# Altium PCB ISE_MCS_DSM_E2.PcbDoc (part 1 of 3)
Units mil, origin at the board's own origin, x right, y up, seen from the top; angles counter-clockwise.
Board outline 7874.02 x 2559.06 mil, 4 copper layers (Top Layer, MidLayer1, MidLayer2, Bottom Layer), stack 61.2 mil thick; 400 components, 190 nets, 1028 pads, 191 vias.
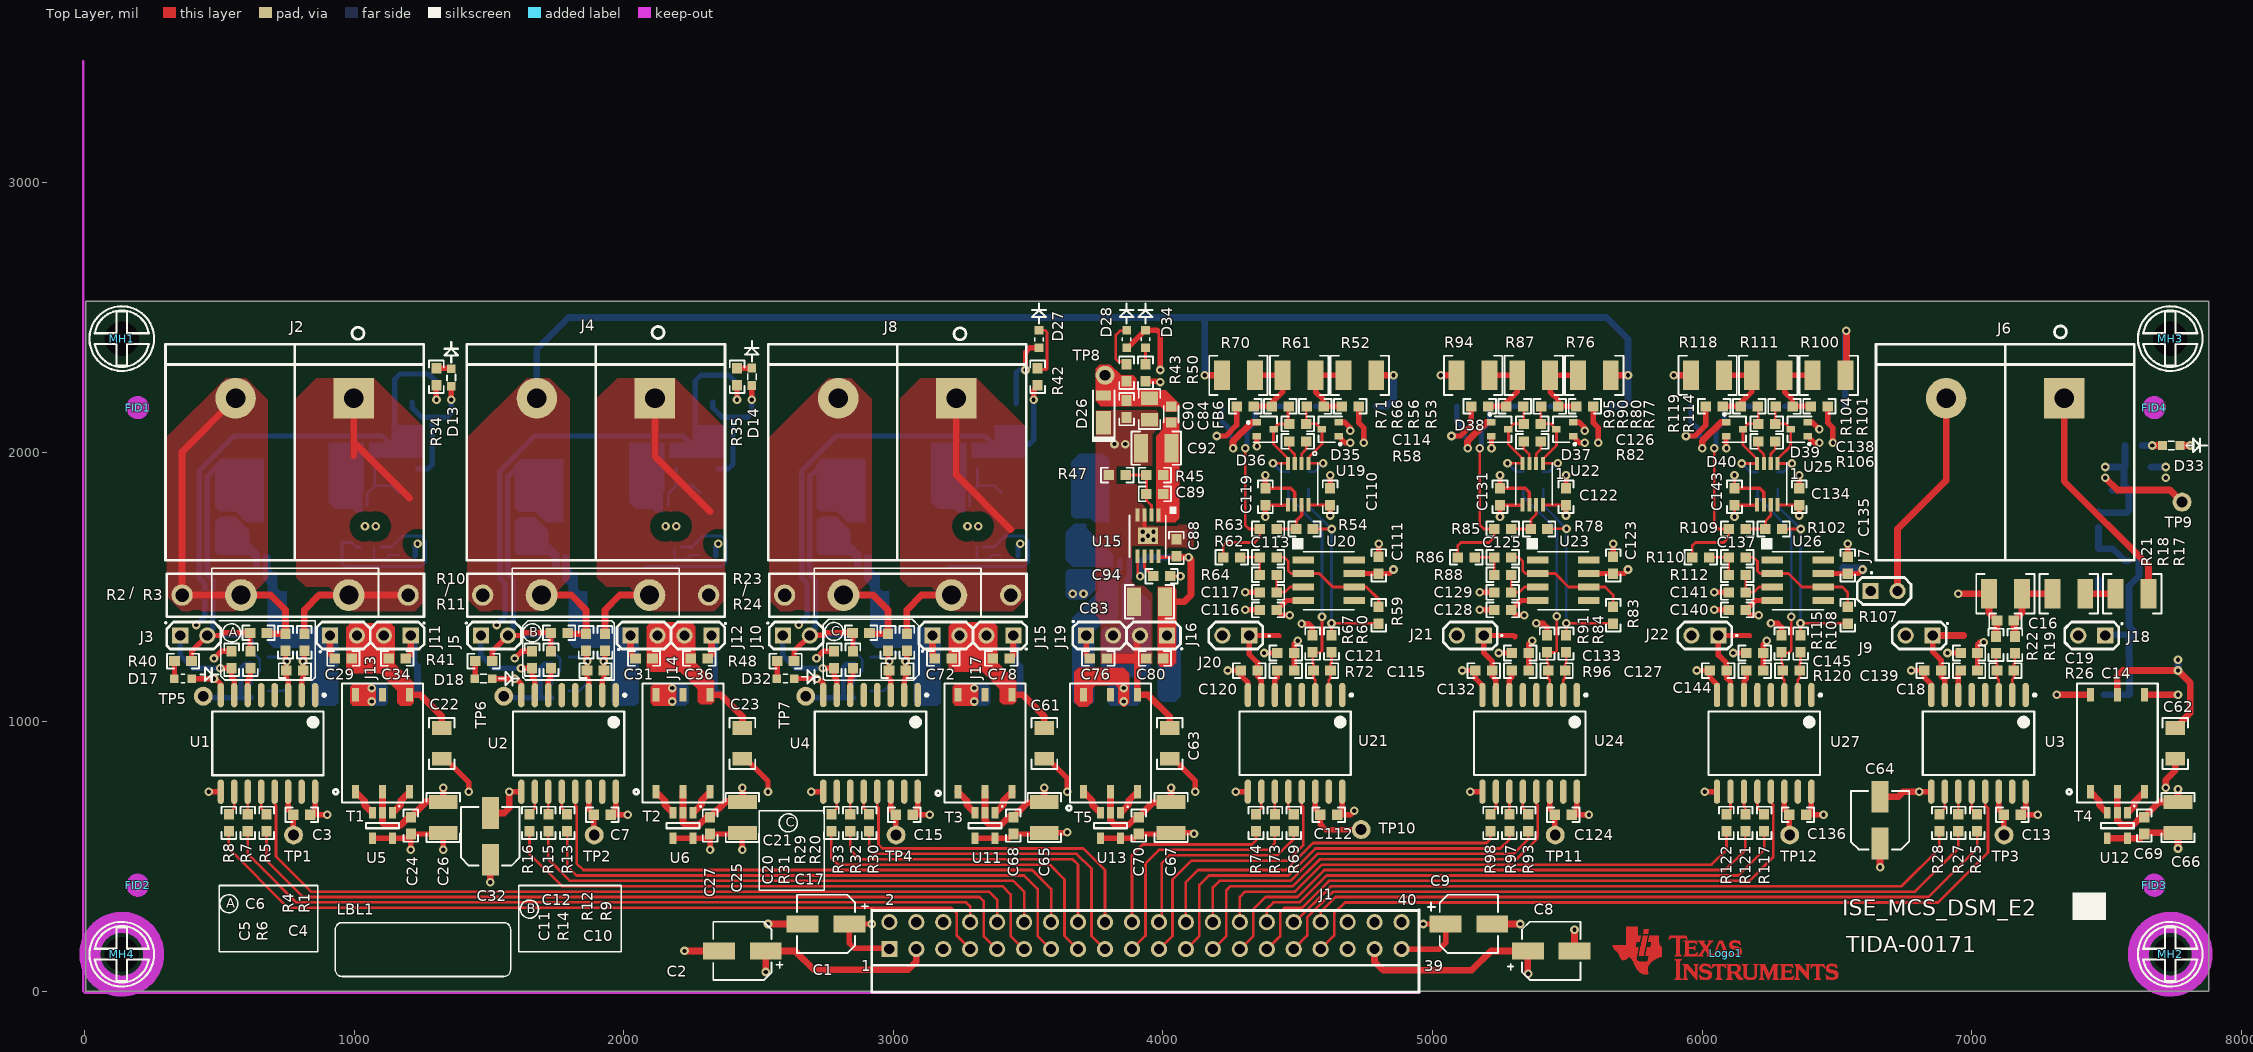
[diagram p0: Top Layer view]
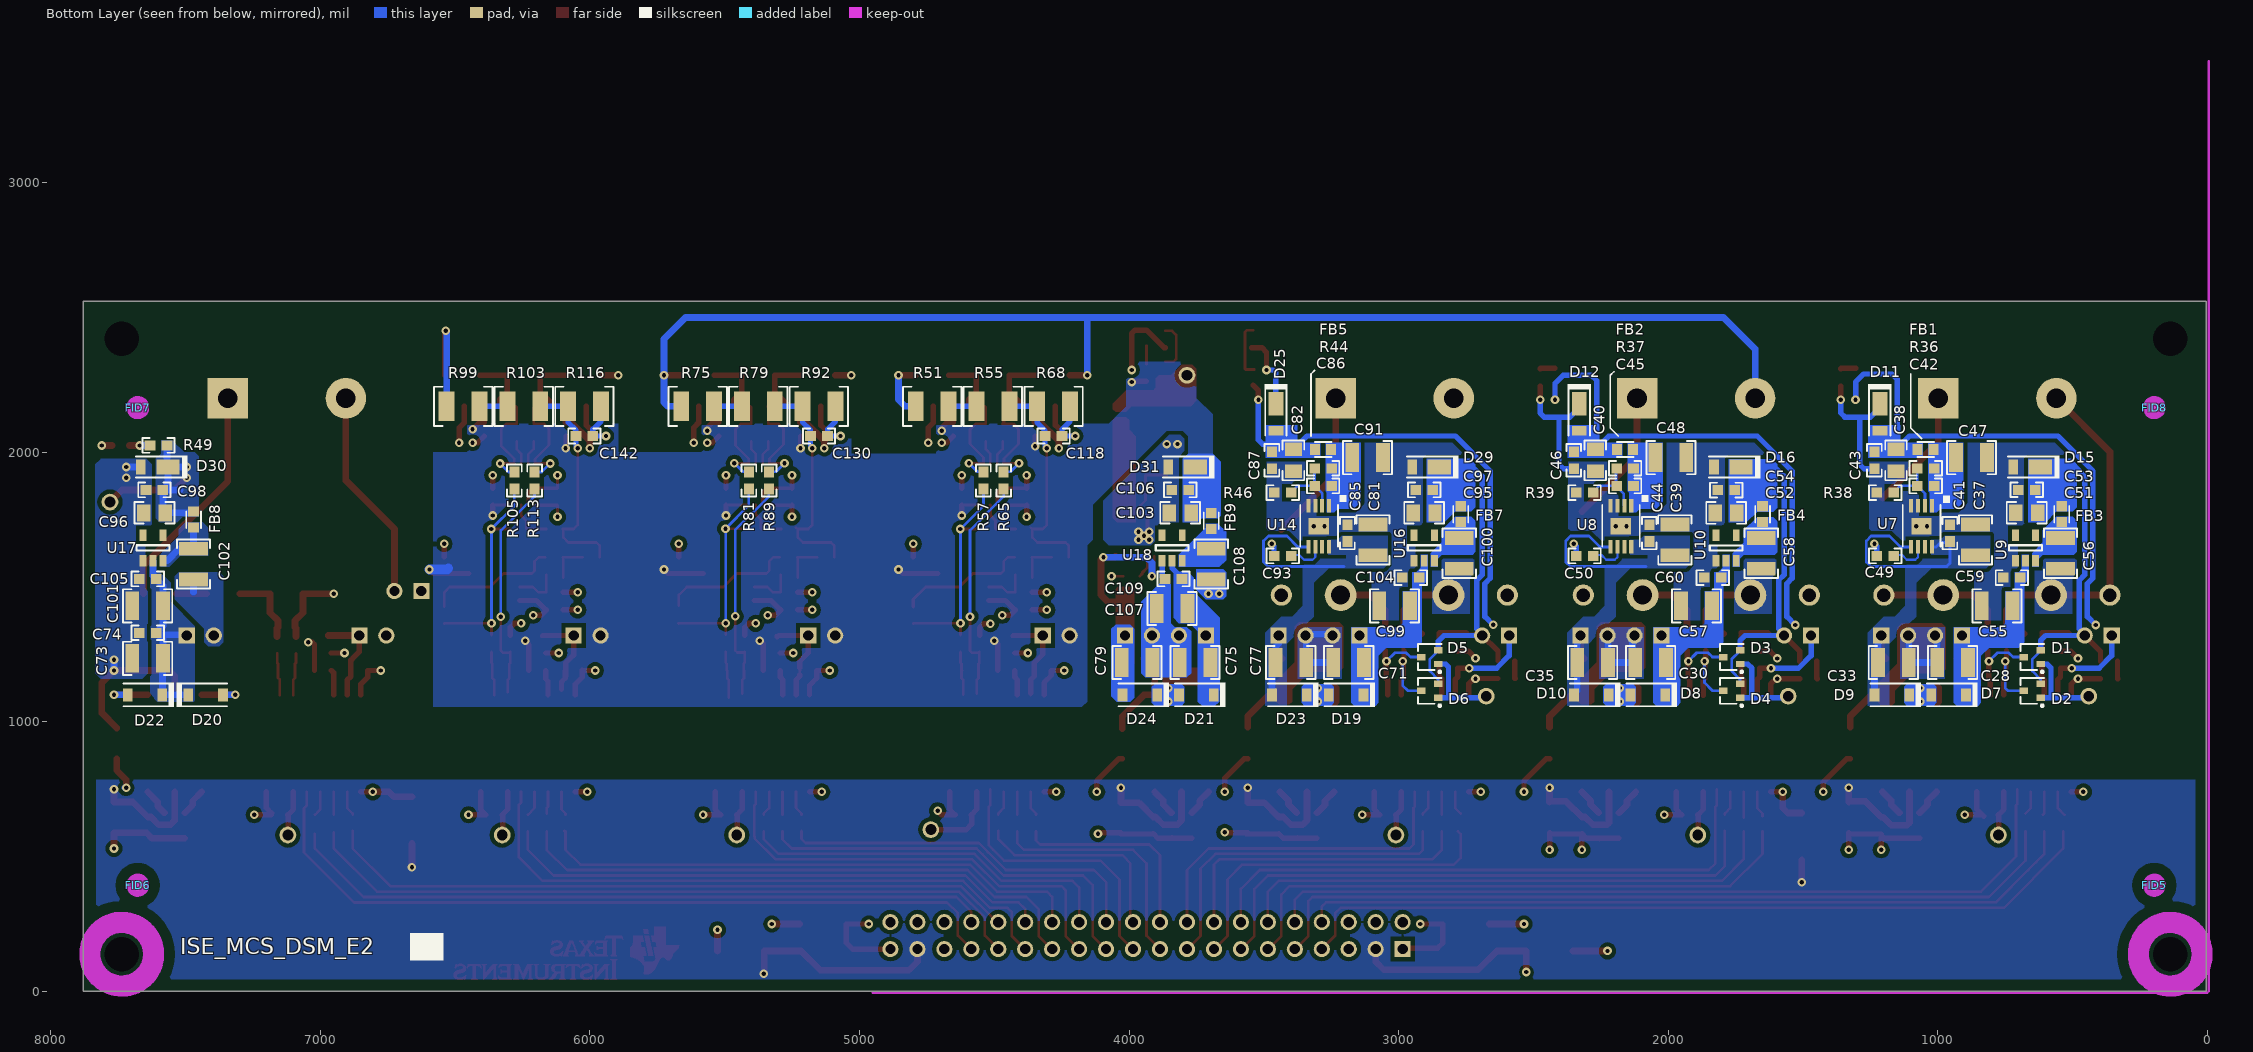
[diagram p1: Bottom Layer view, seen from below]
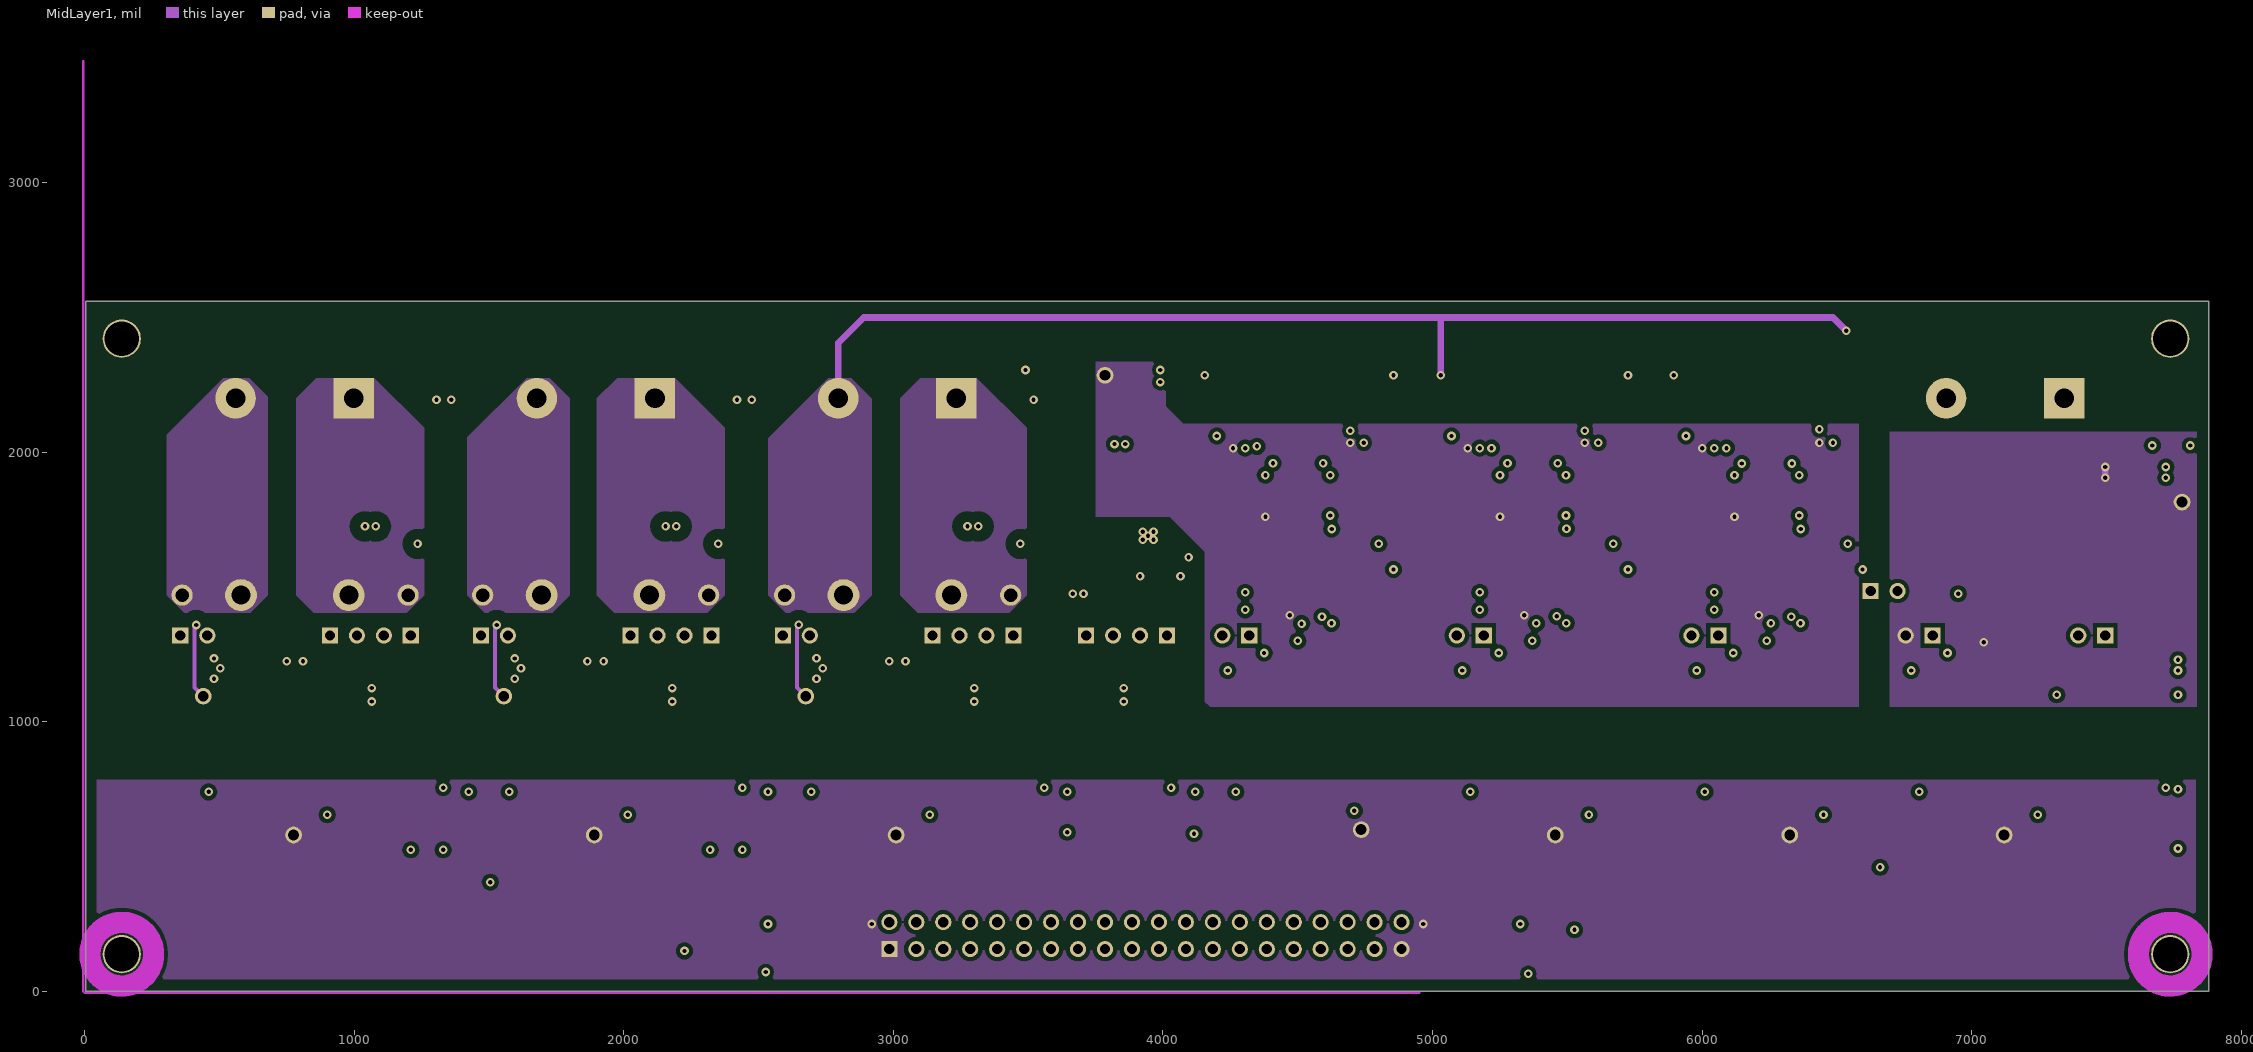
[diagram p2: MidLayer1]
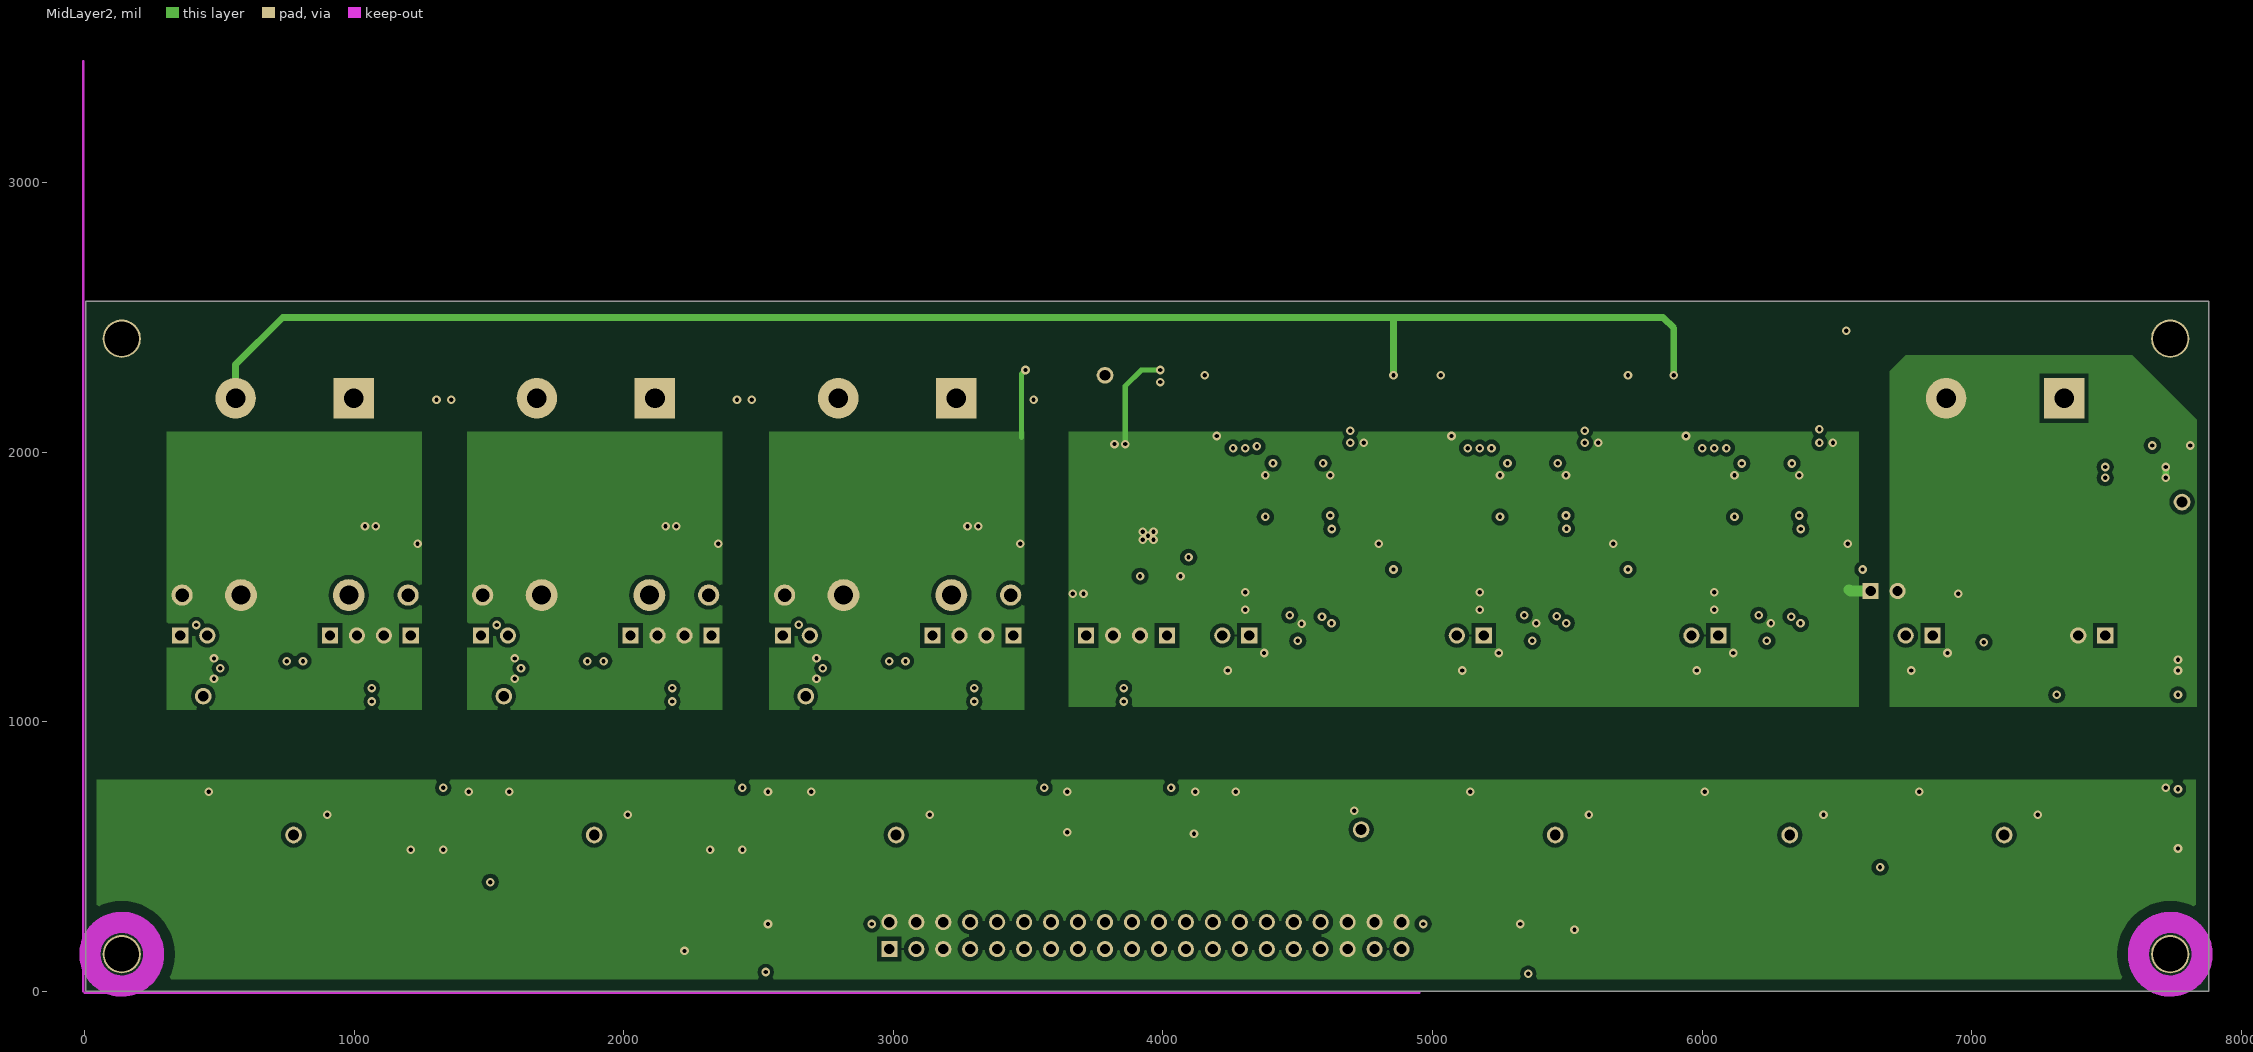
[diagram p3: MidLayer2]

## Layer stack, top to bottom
Top Layer: signal copper 2.8
Dielectric: core 16.6, FR-4, Dk 4.8
MidLayer1: signal copper 2.8
Dielectric: prepreg 16.8, FR-4, Dk 4.8
MidLayer2: signal copper 2.8
Dielectric: core 16.6, FR-4, Dk 4.8
Bottom Layer: signal copper 2.8

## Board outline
5,0 5,2559.06 7879.02,2559.06 7879.02,0

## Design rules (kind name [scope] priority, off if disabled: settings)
AcuteAngle [All] p1 off: minimum=4.50000000000000E+0001 checktracksonly=FALSE
AssemblyTestPointUsage [All] p1 off: valid=2
AssemblyTestpoint [All] p1 off: testpointundercomponent=TRUE minsize=40 maxsize=100 preferedsize=60 minholesize=0 maxholesize=40 preferedholesize=32 testpointgrid=1 usegrid=TRUE gridtolerance=0.01 allowsidetop=TRUE allowsidebottom=TRUE
Clearance Clearance_35 [IsVia vs IsVia] p1: gap=3
Clearance Clearance_34 [InNamedPolygon('MidLayer1-No Net 7')] p2: gap=40
Clearance Clearance_33 [InNamedPolygon('MidLayer1-No Net 6')] p3: gap=40
Clearance Clearance_32 [InNamedPolygon('MidLayer1-No Net 5')] p4: gap=40
Clearance Clearance_31 [InNamedPolygon('Top Layer-No Net 6')] p5: gap=40
Clearance Clearance_30 [InNamedPolygon('Top Layer-No Net 5')] p6: gap=40
Clearance Clearance_29 [InNamedPolygon('Top Layer-No Net 4')] p7: gap=40
Clearance Clearance_28 [InNamedPolygon('MidLayer1-No Net 4')] p8: gap=40
Clearance Clearance_27 [InNamedPolygon('MidLayer1-No Net 3')] p9: gap=40
Clearance Clearance_26 [InNamedPolygon('Top Layer-No Net 3')] p10: gap=40
Clearance Clearance_25 [InNamedPolygon('Top Layer-No Net 2')] p11: gap=40
Clearance Clearance_24 [InNamedPolygon('Top Layer-No Net 1')] p12: gap=40
Clearance Clearance_23 [InNamedPolygon('MidLayer1-No Net 2')] p13: gap=40
Clearance Clearance_22 [InNamedPolygon('MidLayer1-No Net 2')] p14: gap=40
Clearance Clearance_21 [InNamedPolygon('MidLayer1-No Net 2')] p15: gap=15
Clearance Clearance_20 [InNamedPolygon('MidLayer1-No Net 2')] p16: gap=40
Clearance Clearance_19 [InNamedPolygon('MidLayer1-No Net 2')] p17: gap=40
Clearance Clearance_18 [InNamedPolygon('MidLayer1-No Net 2')] p18: gap=15
Clearance Clearance_17 [InNamedPolygon('MidLayer1-No Net 2')] p19: gap=40
Clearance Clearance_16 [InNamedPolygon('MidLayer1-No Net 2')] p20: gap=40
Clearance Clearance_15 [InNamedPolygon('MidLayer1-No Net 2')] p21: gap=40
Clearance Clearance_14 [InNamedPolygon('MidLayer1-No Net 2')] p22: gap=40
Clearance Clearance_13 [InNamedPolygon('MidLayer1-No Net 2')] p23: gap=40
Clearance Clearance_12 [InNamedPolygon('MidLayer1-No Net 2')] p24: gap=40
Clearance Clearance_11 [InNamedPolygon('MidLayer1-No Net 2')] p25: gap=40
Clearance Clearance_10 [InNamedPolygon('MidLayer1-No Net 2')] p26: gap=40
Clearance Clearance_9 [InNamedPolygon('MidLayer1-No Net 2')] p27: gap=15
Clearance Clearance_8 [InNamedPolygon('MidLayer1-No Net 2')] p28: gap=40
Clearance Clearance_7 [InNamedPolygon('MidLayer1-No Net 2')] p29: gap=40
Clearance Clearance_6 [InNamedPolygon('MidLayer1-No Net 2')] p30: gap=40
Clearance Clearance_5 [InNamedPolygon('MidLayer1-No Net 2')] p31: gap=40
Clearance Clearance_4 [InNamedPolygon('MidLayer1-No Net')] p32: gap=15
Clearance Clearance_3 [InNamedPolygon('MidLayer1-No Net')] p33: gap=10
Clearance Clearance_2 [InNamedPolygon('MidLayer1-No Net')] p34: gap=10
Clearance Clearance_1 [InNamedPolygon('MidLayer1-No Net')] p35: gap=40
Clearance Clearance_BoardEdge_MountingHoles [OnCopper and InComponentClass('Mounting Holes') vs IsKeepOut] p36: gap=40
Clearance Clearance_BoardEdge_Poly [OnCopper and InPoly vs IsKeepOut] p37: gap=40
Clearance Clearance_BoardEdge [OnCopper and Not InComponentClass('Logo') and not InComponentClass('FiducialMark') and not InRegion(1000,500,4000,800) and Not IsKeepout vs IsKeepOut] p38: gap=40
Clearance Clearance_Poly [InPolygon] p39: gap=15
Clearance [All] p40: gap=8
ComponentClearance ComponentClearance_Logo [InComponentClass('Logo')] p1 off: gap=50 collisioncheckmode=3 verticalgap=10 showdistances=FALSE
ComponentClearance ComponentClearance_ScrewToNut [(HasFootprint('NY PMS 440 0025 PH')) vs (HasFootprint('Keystone_1902C'))] p2 off: gap=5 collisioncheckmode=3 verticalgap=10 showdistances=FALSE
ComponentClearance ComponentClearance_MountingHoles [InComponentClass('Mounting Holes')] p3 off: gap=250 collisioncheckmode=3 verticalgap=100000 showdistances=FALSE
ComponentClearance ComponentClearance_SmallPassives [HasFootprint('0201*') or HasFootprint('0402*') or HasFootprint('0508') or HasFootprint('0603*') or HasFootprint('0612') or HasFootprint('0805*') or HasFootprint('0815*') or HasFootprint('0830*') or HasFootprint('1206*') or HasFootprint('1210*') or HasFootprint('1808*') or HasFootprint('1812*') or HasFootprint('1825*') or HasFootprint('2010*') or HasFootprint('2220*') or HasFootprint('2225*') or HasFootprint('2512*') or HasFootprint('2728*') or HasFootprint('3518*') vs HasFootprint('0201*') or HasFootprint('0402*') or HasFootprint('0508') or HasFootprint('0603*') or HasFootprint('0612') or HasFootprint('0805*') or HasFootprint('0815*') or HasFootprint('0830*') or HasFootprint('1206*') or HasFootprint('1210*') or HasFootprint('1808*') or HasFootprint('1812*') or HasFootprint('1825*') or HasFootprint('2010*') or HasFootprint('2220*') or HasFootprint('2225*') or HasFootprint('2512*') or HasFootprint('2728*') or HasFootprint('3518*')] p4 off: gap=20 collisioncheckmode=3 verticalgap=10 showdistances=FALSE
ComponentClearance ComponentClearance_THtoSMT [IsThruComponent vs IsSMTComponent] p5 off: gap=100 collisioncheckmode=3 verticalgap=30 showdistances=FALSE
ComponentClearance ComponentClearance_THtoTH [IsThruComponent vs IsThruComponent] p6 off: gap=118.11 collisioncheckmode=3 verticalgap=30 showdistances=FALSE
ComponentClearance [All] p7 off: gap=40 collisioncheckmode=3 verticalgap=10 showdistances=FALSE
DiffPairsRouting DiffPair_RS232DiffPairsRouting [InDifferentialPair ('RS232')] p1: maxlimit=8 minlimit=8 mostfreqgap=8 maxuncoupledlength=500
DiffPairsRouting [All] p2: maxlimit=100 minlimit=10 mostfreqgap=10 maxuncoupledlength=1000
FabricationTestPointUsage TestPointUsage [All] p1 off: valid=2 allowmultiple=FALSE
FabricationTestpoint Testpoint [All] p1 off: side=3 testpointundercomponent=TRUE minsize=40 maxsize=100 preferedsize=60 minholesize=0 maxholesize=40 preferedholesize=32 testpointgrid=1 allowsidetop=TRUE allowsidebottom=TRUE usegrid=TRUE gridtolerance=0.01
FanoutControl Fanout_LCC [IsLCC] p1 off: bgadir=Out bgaviamode=Centered fanoutstyle=Auto fanoutdirection=Alternating viagrid=1 // Fanout_LCC (Default Rule)
FanoutControl Fanout_BGA [IsBGA] p2 off: bgadir=Out bgaviamode=Centered fanoutstyle=Auto fanoutdirection=Alternating viagrid=1 // Fanout_BGA (Default Rule)
FanoutControl Fanout_SOIC [IsSOIC] p3 off: bgadir=Out bgaviamode=Centered fanoutstyle=Auto fanoutdirection=Alternating viagrid=1 // Fanout_SOIC (Default Rule)
FanoutControl Fanout_Default [All] p4 off: bgadir=Out bgaviamode=Centered fanoutstyle=Auto fanoutdirection=Alternating viagrid=1 // Fanout_Default (Default Rule)
FanoutControl Fanout_Small [(CompPinCount < 5)] p5 off: bgadir=Out bgaviamode=Centered fanoutstyle=Auto fanoutdirection=OutThenIn viagrid=1 // Fanout_Small (Default Rule)
Height [All] p1 off: minheight=0 maxheight=1000 prefheight=500
HoleSize [All] p1 off: absolutevalues=TRUE maxlimit=251 minlimit=8 maxpercent=80.000 minpercent=20.000
HoleToHoleClearance [All] p1 off: gap=10 allowstackedmicrovias=TRUE
LayerPairs [All] p1 off: enforce=TRUE
MatchedLengths DiffPair_RS232MatchedLengths [InDifferentialPair ('RS232')] p1: tolerance=1000 checknetsindiffpair=TRUE checkdiffpairvsdiffpair=TRUE checkothers=TRUE
MinimumAnnularRing MinimumAnnularRing_ThermalPadVias [IsVia and InAnyComponent] p1 off: minimumring=5.91
MinimumAnnularRing [All] p2 off: minimumring=8
MinimumSolderMaskSliver MinimumSolderMaskSliver_Logo [InComponentClass('Logo') vs InComponentClass('Logo')] p1 off: minsoldermaskwidth=0.7
MinimumSolderMaskSliver [All] p2 off: minsoldermaskwidth=3.94
NetAntennae [All] p1 off: netantennaetolerance=0
PasteMaskExpansion [All] p1 off: expansion=0
PlaneClearance [All] p1: clearance=15
PlaneConnect [All] p1: planeconnectstyle=Direct reliefexpansion=10 reliefentries=4 reliefconductorwidth=10 reliefairgap=10
PolygonConnect [All] p1: connectstyle=Direct reliefconductorwidth=10 reliefentries=4 polygonreliefangle="90 Angle" airgapwidth=10
RoutingCorners [All] p1 off: cornerstyle=45-Degree minsetback=100 maxsetback=100
RoutingLayers [All] p1 off: top layer_v5=TRUE mid layer 1_v5=TRUE mid layer 2_v5=TRUE bottom layer_v5=TRUE
RoutingPriority [All] p1 off: routingpriority=0
RoutingTopology [All] p1 off: topology=Shortest
RoutingVias ThermalPadVias [IsVia and InAnyComponent] p1: holewidth=16 width=32 viastyle="Through Hole" minholewidth=16 minwidth=32 maxholewidth=16 maxwidth=32
RoutingVias [All] p2: holewidth=16 width=32 viastyle="Through Hole" minholewidth=16 minwidth=32 maxholewidth=16 maxwidth=32
SMDToCorner [All] p1 off: distance=30000
SilkToSilkClearance [All] p1 off: silktosilkclearance=5
SilkscreenOverComponentPads [All] p1 off: minsilkscreentomaskgap=5
SolderMaskExpansion [All] p1 off: expansion=1.97
Width DiffPair_RS232Width [InDifferentialPair('RS232')] p1: maxlimit=10 minlimit=10 preferedwidth=10
Width [All] p2: maxlimit=100 minlimit=8 preferedwidth=25 checkconnectedcopper=TRUE
2 further rules are at their usual default settings.

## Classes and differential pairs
component class "Current Sense": C1 C2 C3 C4 C5 C6 C7 C8 C9 C10 C11 C12 C13 C14 C15 C16 C17 C18 C19 C20 C21 D1 D2 D3 D4 D5 D6 J1 J2 J3 J4 J5 J6 J7 J8 J9 J10 R1 R2 R3 R4 R5 R6 R7 R8 R9 R10 R11 R12 R13 R14 R15 R16 R17 R18 R19 R20 R21 R22 R23 R24 R25 R26 R27 R28 R29 R30 R31 R32 R33 TP1 TP2 TP3 TP4 U1 U2 U3 U4
component class "Mounting Holes": MH1 MH2 MH3 MH4
component class Logo: Logo1
component class Hardware: FID1 FID2 FID3 FID4 FID5 FID6 FID7 FID8 LBL1 Logo1 MH1 MH2 MH3 MH4 ZZ1 ZZ2 ZZ3 ZZ4
component class FiducialMark: FID1 FID2 FID3 FID4 FID5 FID6 FID7 FID8
component class AssemblyNote: ZZ1 ZZ2 ZZ3 ZZ4
component class Label: LBL1
component class "Voltage signal conditioning": C110 C111 C112 C113 C114 C115 C116 C117 C118 C119 C120 C121 C122 C123 C124 C125 C126 C127 C128 C129 C130 C131 C132 C133 C134 C135 C136 C137 C138 C139 C140 C141 C142 C143 C144 C145 D35 D36 D37 D38 D39 D40 J20 J21 J22 R51 R52 R53 R54 R55 R56 R57 R58 R59 R60 R61 R62 R63 R64 R65 R66 R67 R68 R69 R70 R71 R72 R73 R74 R75 R76 R77 R78 R79 R80 R81 R82 R83 R84 R85 R86 R87 R88 R89 R90 R91 R92 R93 R94 R95 R96 R97 R98 R99 R100 R101 R102 R103 R104 R105 R106 R107 R108 R109 R110 R111 R112 R113 R114 R115 R116 R117 R118 R119 R120 R121 R122 TP10 TP11 TP12 U19 U20 U21 U22 U23 U24 U25 U26 U27
component class "Power supply 1": C22 C23 C24 C25 C26 C27 C28 C29 C30 C31 C32 C33 C34 C35 C36 C37 C38 C39 C40 C41 C42 C43 C44 C45 C46 C47 C48 C49 C50 C51 C52 C53 C54 C55 C56 C57 C58 C59 C60 D7 D8 D9 D10 D11 D12 D13 D14 D15 D16 D17 D18 FB1 FB2 FB3 FB4 J11 J12 J13 J14 R34 R35 R36 R37 R38 R39 R40 R41 T1 T2 TP5 TP6 U5 U6 U7 U8 U9 U10
component class "Power supply 2": C61 C62 C63 C64 C65 C66 C67 C68 C69 C70 C71 C72 C73 C74 C75 C76 C77 C78 C79 C80 C81 C82 C83 C84 C85 C86 C87 C88 C89 C90 C91 C92 C93 C94 C95 C96 C97 C98 C99 C100 C101 C102 C103 C104 C105 C106 C107 C108 C109 D19 D20 D21 D22 D23 D24 D25 D26 D27 D28 D29 D30 D31 D32 D33 D34 FB5 FB6 FB7 FB8 FB9 J15 J16 J17 J18 J19 R42 R43 R44 R45 R46 R47 R48 R49 R50 T3 T4 T5 TP7 TP8 TP9 U11 U12 U13 U14 U15 U16 U17 U18

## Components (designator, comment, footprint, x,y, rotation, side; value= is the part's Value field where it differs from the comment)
C1 "UUD1E220MCL1GS" SM_RADIAL_5MM 2750,250 r180 top
C2 "UUD1E220MCL1GS" SM_RADIAL_5MM 2440,150 r180 top
C3 "" 0603 805,655 r180 top
C4 "C1608C0G1E392J" 0603 780,1190 r180 top
C5 "" 0603 545,1230 r90 top
C6 "" 0603 645,1330 r0 top
C7 "" 0603 1920,655 r180 top
C8 "UUD1E220MCL1GS" SM_RADIAL_5MM 5440,150 r0 top
C9 "UUD1E220MCL1GS" SM_RADIAL_5MM 5135,250 r0 top
C10 "C1608C0G1E392J" 0603 1895,1190 r180 top
C11 "" 0603 1660,1230 r90 top
C12 "" 0603 1760,1330 r0 top
C13 "" 0603 7150,655 r180 top
C14 "" 0603 7125,1190 r180 top
C15 "" 0603 3040,655 r180 top
C16 "" 0603 7125,1375 r0 top
C17 "C1608C0G1E392J" 0603 3015,1190 r180 top
C18 "" 0603 6855,1190 r180 top
C19 "" 0603 6990,1255 r180 top
C20 "" 0603 2780,1230 r90 top
C21 "" 0603 2880,1330 r0 top
C22 "" 1206 1325,920 r90 top
C23 "" 1206 2440,920 r90 top
C24 "" 1210 1330,645 r90 top
C25 "" 1210 2440,645 r90 top
C26 "" 0603 1210,615 r90 top
C27 "" 0603 2320,615 r90 top
C28 "" 1210 945,1220 r0 bottom
C29 "" 0603 960,1235 r0 top
C30 "" 1210 2065,1220 r0 bottom
C31 "" 0603 2075,1235 r0 top
C32 "UUD1E220MCL1GS" SM_RADIAL_5MM 1505,575 r90 top
C33 "" 1210 1165,1220 r0 bottom
C34 "" 0603 1160,1235 r0 top
C35 "" 1210 2280,1220 r0 bottom
C36 "" 0603 2280,1235 r0 top
C37 "" 1210 860,1675 r270 bottom
C38 "" 0805_HV 1155,1970 r90 bottom
C39 "" 1210 1975,1675 r270 bottom
C40 "" 0805_HV 2270,1970 r90 bottom
C41 "" 0603 955,1700 r90 bottom
C42 "" 0603 1045,1875 r180 bottom
C43 "" 0603 1235,1970 r270 bottom
C44 "" 0603 2070,1700 r90 bottom
C45 "" 0603 2160,1875 r180 bottom
C46 "" 0603 2350,1970 r270 bottom
C47 "" 1210 875,1980 r0 bottom
C48 "" 1210 1990,1980 r0 bottom
C49 "" 0603 1195,1615 r180 bottom
C50 "" 0603 2310,1615 r180 bottom
C51 "" 0805_HV 670,1775.32 r180 bottom
C52 "" 0805_HV 1785,1774.5 r180 bottom
C53 "" 0603 670,1860.32 r0 bottom
C54 "" 0603 1785,1859.5 r0 bottom
C55 "" 1210 780,1430 r180 bottom
C56 "" 1210 545,1625 r90 bottom
C57 "" 1210 1895,1430 r180 bottom
C58 "" 1210 1655,1625 r90 bottom
C59 "" 0603 725,1535 r0 bottom
C60 "" 0603 1835,1535 r0 bottom
C61 "" 1206 3560,920 r90 top
C62 "" 1206 7755,920 r90 top
C63 "" 1206 4025,920 r90 top
C64 "UUD1E220MCL1GS" SM_RADIAL_5MM 6660,635 r90 top
C65 "" 1210 3560,645 r90 top
C66 "" 1210 7765,645 r90 top
C67 "" 1210 4030,645 r90 top
C68 "" 0603 3445,615 r90 top
C69 "" 0603 7640,615 r90 top
C70 "" 0603 3910,615 r90 top
C71 "" 1210 3185,1220 r0 bottom
C72 "" 0603 3185,1235 r0 top
C73 "" 1210 7640,1235 r0 bottom
C74 "" 0603 7640,1330 r0 bottom
C75 "" 1210 3755,1220 r0 bottom
C76 "" 0603 3760,1235 r0 top
C77 "" 1210 3400,1220 r0 bottom
C78 "" 0603 3400,1235 r0 top
C79 "" 1210 3970,1220 r0 bottom
C80 "" 0603 3970,1235 r0 top
C81 "" 1210 3095,1675 r270 bottom
C82 "" 0805_HV 3390,1970 r90 bottom
C83 "" 1210 3950,1445 r0 top
C84 "" 0805_HV 3950,2160 r90 top
C85 "" 0603 3190,1700 r90 bottom
C86 "" 0603 3280,1875 r180 bottom
C87 "" 0603 3470,1970 r270 bottom
C88 "" 0603 4050,1645 r90 top
C89 "" 0603 3970,1845 r0 top
C90 "" 0603 3865,2160 r270 top
C91 "" 1210 3115,1980 r0 bottom
C92 "" 1210 3975,2015 r0 top
C93 "" 0603 3430,1615 r180 bottom
C94 "" 0603 3995,1540 r180 top
C95 "" 0805_HV 2905,1775 r180 bottom
C96 "" 0805_HV 7615,1775 r180 bottom
C97 "" 0603 2905,1860 r0 bottom
C98 "" 0603 7615,1860 r0 bottom
C99 "" 1210 3015,1430 r180 bottom
C100 "" 1210 2775,1625 r90 bottom
C101 "" 1210 7640,1430 r180 bottom
C102 "" 1210 7470,1585 r90 bottom
C103 "" 0805_HV 3810,1775 r180 bottom
C104 "" 0603 2955,1535 r0 bottom
C105 "" 0603 7640,1530 r0 bottom
C106 "" 0603 3810,1860 r0 bottom
C107 "" 1210 3840,1420 r180 bottom
C108 "" 1210 3695,1585 r90 bottom
C109 "" 0603 3835,1530 r0 bottom
C110 "" 0603 4620,1835 r270 top
C111 "" 0603 4800,1580 r270 top
C112 "" 0603 4615,655 r180 top
C113 "" 0603 4390,1610 r0 top
C114 "C1608C0G1E392J" 0603 4500,2105 r180 top
C115 "" 0603 4590,1190 r180 top
C116 "" 0603 4390,1415 r0 top
C117 "" 0603 4390,1480 r180 top
C118 "" 0603 4280,2060 r0 bottom
C119 "" 0603 4380,1835 r270 top
C120 "" 0603 4320,1190 r180 top
C121 "" 0603 4455,1255 r180 top
C122 "" 0603 5495,1835 r270 top
C123 "" 0603 5670,1580 r270 top
C124 "" 0603 5485,655 r180 top
C125 "" 0603 5260,1610 r0 top
C126 "C1608C0G1E392J" 0603 5370,2105 r180 top
C127 "" 0603 5460,1190 r180 top
C128 "" 0603 5260,1415 r0 top
C129 "" 0603 5260,1480 r180 top
C130 "" 0603 5150,2060 r0 bottom
C131 "" 0603 5250,1835 r270 top
C132 "" 0603 5190,1190 r180 top
C133 "" 0603 5325,1255 r180 top
C134 "" 0603 6360,1835 r270 top
C135 "" 0603 6540,1580 r270 top
C136 "" 0603 6355,655 r180 top
C137 "" 0603 6130,1610 r0 top
C138 "C1608C0G1E392J" 0603 6240,2105 r180 top
C139 "" 0603 6330,1190 r180 top
C140 "" 0603 6130,1415 r0 top
C141 "" 0603 6130,1480 r180 top
C142 "" 0603 6020,2060 r0 bottom
C143 "" 0603 6120,1835 r270 top
C144 "" 0603 6060,1190 r180 top
C145 "" 0603 6195,1255 r180 top
D1 "" SOT-323 650,1240 r0 bottom
D2 "" SOT-323 650,1115 r0 bottom
D3 "DESD1P0RFW-7" SOT-323 1765,1240 r0 bottom
D4 "DESD1P0RFW-7" SOT-323 1765,1115 r0 bottom
D5 "DESD1P0RFW-7" SOT-323 2885,1240 r0 bottom
D6 "DESD1P0RFW-7" SOT-323 2885,1115 r0 bottom
D7 "MBR0520LT1G" SOD-123 960,1100 r0 bottom
D8 "MBR0520LT1G" SOD-123 2075,1100 r0 bottom
D9 "MBR0520LT1G" SOD-123 1170,1100 r0 bottom
D10 "MBR0520LT1G" SOD-123 2285,1100 r0 bottom
D11 "" powerDI123 1215,2130 r270 bottom
D12 "" powerDI123 2330,2130 r270 bottom
D13 "" LED0603AA 1360,2277 r270 top
D14 "" LED0603AA 2475,2280 r270 top
D15 "" powerDI123 670,1945 r0 bottom
D16 "" powerDI123 1780,1945 r0 bottom
D17 "" LED0603AA 365,1160 r180 top
D18 "" LED0603AA 1480,1160 r180 top
D19 "MBR0520LT1G" SOD-123 3195,1100 r0 bottom
D20 "MBR0520LT1G" SOD-123 7425,1100 r180 bottom
D21 "MBR0520LT1G" SOD-123 3750,1100 r0 bottom
D22 "MBR0520LT1G" SOD-123 7650,1100 r0 bottom
D23 "MBR0520LT1G" SOD-123 3405,1100 r0 bottom
D24 "MBR0520LT1G" SOD-123 3960,1100 r0 bottom
D25 "" powerDI123 3455,2130 r270 bottom
D26 "" powerDI123 3780,2160 r90 top
D27 "" LED0603AA 3540,2420 r270 top
D28 "" LED0603AA 3865,2420 r270 top
D29 "" powerDI123 2900,1945 r0 bottom
D30 "" powerDI123 7615,1945 r0 bottom
D31 "" powerDI123 3805,1945 r0 bottom
D32 "" LED0603AA 2600,1160 r180 top
D33 "" LED0603AA 7740,2025 r180 top
D34 "" LED0603AA 3935,2420 r270 top
D35 "DESD1P0RFW-7" SOT-323 4620,2085 r180 top
D36 "DESD1P0RFW-7" SOT-323 4380,2085 r0 top
D37 "DESD1P0RFW-7" SOT-323 5490,2085 r180 top
D38 "DESD1P0RFW-7" SOT-323 5250,2085 r0 top
D39 "DESD1P0RFW-7" SOT-323 6360,2085 r180 top
D40 "DESD1P0RFW-7" SOT-323 6120,2085 r0 top
FB1 "" FB0603 1045,2010 r0 bottom
FB2 "" FB0603 2160,2010 r0 bottom
FB3 "" FB0603 540,1770 r90 bottom
FB4 "" FB0603 1650,1770 r90 bottom
FB5 "" FB0603 3280,2010 r0 bottom
FB6 "" FB0603 4030,2140 r90 top
FB7 "" FB0603 2770,1770 r90 bottom
FB8 "" FB0603 7470,1750 r90 bottom
FB9 "" FB0603 3695,1745 r90 bottom
FID1 "" Fiducial10-20 196.85,2165.35 r0 top
FID2 "" Fiducial10-20 196.85,393.7 r0 top
FID3 "" Fiducial10-20 7677.17,393.7 r0 top
FID4 "" Fiducial10-20 7677.17,2165.35 r90 top
FID5 "" Fiducial10-20 196.85,393.7 r180 bottom
FID6 "" Fiducial10-20 7677.17,393.7 r180 bottom
FID7 "" Fiducial10-20 7677.17,2165.35 r180 bottom
FID8 "" Fiducial10-20 196.85,2165.35 r180 bottom
J1 "61304021021" CONN_61304021021 3937.01,206.69 r180 top
J2 "CON-5-1437657-7" 5-1437657-7 560,2200 r0 top
J3 "" HDR100_1X2 355,1320 r0 top
J4 "CON-5-1437657-7" 5-1437657-7 1677.4,2200 r0 top
J5 "" HDR100_1X2 1470,1320 r0 top
J6 "CON-5-1437657-7" 5-1437657-7 6905,2200 r0 top
J7 "" HDR100_1X2 6625,1485 r0 top
J8 "CON-5-1437657-7" 5-1437657-7 2795.51,2200 r0 top
J9 "" HDR100_1X2 6855,1320 r180 top
J10 "" HDR100_1X2 2590,1320 r0 top
J11 "" HDR100_1X2 1210,1320 r180 top
J12 "" HDR100_1X2 2325,1320 r180 top
J13 "" HDR100_1X2 910,1320 r0 top
J14 "" HDR100_1X2 2025,1320 r0 top
J15 "" HDR100_1X2 3445,1320 r180 top
J16 "" HDR100_1X2 4015,1320 r180 top
J17 "" HDR100_1X2 3145,1320 r0 top
J18 "" HDR100_1X2 7495,1320 r180 top
J19 "" HDR100_1X2 3715,1320 r0 top
J20 "" HDR100_1X2 4320,1320 r180 top
J21 "" HDR100_1X2 5190,1320 r180 top
J22 "" HDR100_1X2 6060,1320 r180 top
LBL1 "" Label_650x200 1255,155 r180 top
Logo1 "" TI_Stacked_SolderMask_Small 6087,141 r0 top
MH1 "" MH3.2 137.8,2421.26 r0 top
MH2 "" MH3.2 7736.22,137.8 r0 top locked
MH3 "" MH3.2 7736.22,2421.26 r0 top
MH4 "" MH3.2 137.8,137.8 r0 top locked
R1 "RC0603FR-07100RL" 0603 815,1295 r270 top
R2 "PBH-R050-F1-0.5" R_TO-247 580,1470 r0 top
R3 "OAR5R005FLF" PWR4413D-R050F 1200,1470 r180 top
R4 "RC0603FR-07100RL" 0603 745,1295 r270 top
R5 "" 0603 675,625 r270 top
R6 "" 0603 615,1230 r270 top
R7 "" 0603 605,625 r270 top
R8 "" 0603 535,625 r270 top
R9 "RC0603FR-07100RL" 0603 1930,1295 r270 top
R10 "PBH-R050-F1-0.5" R_TO-247 1695,1470 r0 top
R11 "OAR5R005FLF" PWR4413D-R050F 2315,1470 r180 top
R12 "RC0603FR-07100RL" 0603 1860,1295 r270 top
R13 "" 0603 1790,625 r270 top
R14 "" 0603 1730,1230 r270 top
R15 "" 0603 1720,625 r270 top
R16 "" 0603 1650,625 r270 top
R17 "" 1210M 7595,1475 r180 top
R18 "" 1210M 7360,1475 r180 top
R19 "CRCW06030000Z0EA" 0603 7160,1285 r270 top
R20 "RC0603FR-07100RL" 0603 3050,1295 r270 top
R21 "" 1210M 7125,1475 r180 top
R22 "RT0603DRE072KL" 0603 7090,1285 r270 top
R23 "PBH-R050-F1-0.5" R_TO-247 2815,1470 r0 top
R24 "OAR5R005FLF" PWR4413D-R050F 3435,1470 r180 top
R25 "" 0603 7020,625 r270 top
R26 "" 0603 6990,1190 r180 top
R27 "" 0603 6950,625 r270 top
R28 "" 0603 6880,625 r270 top
R29 "RC0603FR-07100RL" 0603 2980,1295 r270 top
R30 "" 0603 2910,625 r270 top
R31 "" 0603 2850,1230 r270 top
R32 "" 0603 2840,625 r270 top
R33 "" 0603 2770,625 r270 top
R34 "" 0603 1305,2280 r270 top
R35 "" 0603 2420,2280 r270 top
R36 "" 0603 1045,1940 r180 bottom
R37 "" 0603 2160,1940 r180 bottom
R38 "" 0603 1195,1850 r180 bottom
R39 "" 0603 2310,1850 r180 bottom
R40 "" 0603 365,1225 r0 top
R41 "" 0603 1480,1225 r0 top
R42 "" 0603 3535,2280 r270 top
R43 "" 0603 3865,2295 r270 top
R44 "" 0603 3280,1940 r180 bottom
R45 "" 0603 3970,1915 r0 top
R46 "" 0603 3430,1850 r180 bottom
R47 "" 0603 3830,1915 r0 top
R48 "" 0603 2600,1225 r0 top
R49 "" 0603 7600,2025 r180 bottom
R50 "" 0603 3935,2295 r270 top
R51 "" 1210M 4730,2170 r180 bottom
R52 "" 1210M 4730,2285 r180 top
R53 "" 0603 4695,2170 r0 top
R54 "" 0603 4525,1715 r0 top
R55 "" 1210M 4505,2170 r180 bottom
R56 "RC0603FR-0756RL" 0603 4565,2170 r180 top
R57 "" 0603 4540,1895 r270 bottom
R58 "" 0603 4500,2040 r0 top
R59 "" 0603 4800,1395 r270 top
R60 "CRCW06030000Z0EA" 0603 4625,1290 r270 top
R61 "" 1210M 4505,2285 r180 top
R62 "" 0603 4255,1610 r0 top
R63 "" 0603 4390,1715 r180 top
R64 "" 0603 4390,1545 r0 top
R65 "" 0603 4465,1895 r270 bottom
R66 "RC0603FR-0756RL" 0603 4435,2170 r0 top
R67 "" 0603 4555,1290 r90 top
R68 "" 1210M 4280,2170 r180 bottom
R69 "" 0603 4485,625 r270 top
R70 "" 1210M 4280,2285 r180 top
R71 "" 0603 4305,2170 r0 top
R72 "" 0603 4455,1190 r180 top
R73 "" 0603 4415,625 r270 top
R74 "" 0603 4345,625 r270 top
R75 "" 1210M 5600,2170 r180 bottom
R76 "" 1210M 5600,2285 r180 top
R77 "" 0603 5565,2170 r0 top
R78 "" 0603 5395,1715 r0 top
R79 "" 1210M 5375,2170 r180 bottom
R80 "RC0603FR-0756RL" 0603 5435,2170 r180 top
R81 "" 0603 5410,1895 r270 bottom
R82 "" 0603 5370,2040 r0 top
R83 "" 0603 5670,1395 r270 top
R84 "CRCW06030000Z0EA" 0603 5495,1290 r270 top
R85 "" 0603 5260,1715 r180 top
R86 "" 0603 5125,1610 r0 top
R87 "" 1210M 5375,2285 r180 top
R88 "" 0603 5260,1545 r0 top
R89 "" 0603 5335,1895 r270 bottom
R90 "RC0603FR-0756RL" 0603 5305,2170 r0 top
R91 "" 0603 5425,1290 r90 top
R92 "" 1210M 5150,2170 r180 bottom
R93 "" 0603 5355,625 r270 top
R94 "" 1210M 5150,2285 r180 top
R95 "" 0603 5175,2170 r0 top
R96 "" 0603 5325,1190 r180 top
R97 "" 0603 5285,625 r270 top
R98 "" 0603 5215,625 r270 top
R99 "" 1210M 6470,2170 r180 bottom
R100 "" 1210M 6470,2285 r180 top
R101 "" 0603 6435,2170 r0 top
R102 "" 0603 6265,1715 r0 top
R103 "" 1210M 6245,2170 r180 bottom
R104 "RC0603FR-0756RL" 0603 6305,2170 r180 top
R105 "" 0603 6280,1895 r270 bottom
R106 "" 0603 6240,2040 r0 top
R107 "" 0603 6540,1395 r270 top
R108 "CRCW06030000Z0EA" 0603 6365,1290 r270 top
R109 "" 0603 6130,1715 r180 top
R110 "" 0603 5995,1610 r0 top
R111 "" 1210M 6245,2285 r180 top
R112 "" 0603 6130,1545 r0 top
R113 "" 0603 6205,1895 r270 bottom
R114 "RC0603FR-0756RL" 0603 6175,2170 r0 top
R115 "" 0603 6295,1290 r90 top
R116 "" 1210M 6020,2170 r180 bottom
R117 "" 0603 6230,625 r270 top
R118 "" 1210M 6020,2285 r180 top
R119 "" 0603 6045,2170 r0 top
R120 "" 0603 6195,1190 r180 top
R121 "" 0603 6160,625 r270 top
R122 "" 0603 6090,625 r270 top
T1 "TRNSFMR 760390015" 760390015 1005,740 r90 top
T2 "TRNSFMR 760390015" 760390015 2120,740 r90 top
T3 "TRNSFMR 760390015" 760390015 3240,740 r90 top
T4 "TRNSFMR 760390015" 760390015 7440,740 r90 top
T5 "TRNSFMR 760390015" 760390015 3705,740 r90 top
TP1 "" TP-040_RND 775,580 r0 top
TP2 "" TP-040_RND 1890,580 r0 top
TP3 "" TP-040_RND 7120,580 r90 top
TP4 "" TP-040_RND 3010,580 r0 top
TP5 "" TP-040_RND 440,1095 r90 top
TP6 "" TP-040_RND 1555,1095 r90 top
TP7 "" TP-040_RND 2675,1095 r90 top
TP8 "" TP-040_RND 3785,2285 r0 top
TP9 "" TP-040_RND 7780,1815 r0 top
TP10 "" TP-040_RND 4735,600 r0 top
TP11 "" TP-040_RND 5455,580 r90 top
TP12 "" TP-040_RND 6325,580 r180 top
U1 "AMC1304L25" DW0016A_N 680,919.69 r270 top
U2 "AMC1304L25" DW0016A_N 1795,919.68 r270 top
U3 "AMC1304L25" DW0016A_N 7025,920 r270 top
U4 "AMC1304L25" DW0016A_N 2915,920 r270 top
U5 "SN6501DBV" DBV0005A_N 1105,615 r270 top
U6 "SN6501DBV" DBV0005A_N 2220,615 r270 top
U7 "TPS7A3001DGNR" MSOP8(DGN) 1060,1725 r270 bottom
U8 "" MSOP8(DGN) 2175,1725 r270 bottom
U9 "TLV70450DBV" DBV0005A_N 675,1645 r90 bottom
U10 "TLV70450DBV" DBV0005A_N 1785,1644.5 r90 bottom
U11 "SN6501DBV" DBV0005A_N 3340,615 r270 top
U12 "SN6501DBV" DBV0005A_N 7540,615 r270 top
U13 "SN6501DBV" DBV0005A_N 3805,615 r270 top
U14 "" MSOP8(DGN) 3295.8,1725 r270 bottom
U15 "" MSOP8(DGN) 3945,1690 r270 top
U16 "TLV70450DBV" DBV0005A_N 2905,1645 r90 bottom
U17 "TLV70450DBV" DBV0005A_N 7620,1645 r90 bottom
U18 "TLV70450DBV" DBV0005A_N 3840,1645 r90 bottom
U19 "INA826IADGK" DGK8 4500,1880 r270 top
U20 "OPA21AID" SO8 4615,1525 r0 top
U21 "AMC1304L25" DW0016A_N 4490,920 r270 top
U22 "INA826IADGK" DGK8 5370,1880 r270 top
U23 "OPA21AID" SO8 5485,1525 r0 top locked
U24 "AMC1304L25" DW0016A_N 5360,920 r270 top
U25 "INA826IADGK" DGK8 6240,1880 r270 top
U26 "OPA21AID" SO8 6355,1525 r0 top
U27 "AMC1304L25" DW0016A_N 6230,920 r270 top
ZZ1 "" AssemblyNoteLabel 284.37,6064.77 r0 top
ZZ2 "" AssemblyNote 284.37,5955.89 r0 top
ZZ3 "" AssemblyNote 284.37,5867.33 r0 top
ZZ4 "" AssemblyNote 284.37,5778.77 r0 top

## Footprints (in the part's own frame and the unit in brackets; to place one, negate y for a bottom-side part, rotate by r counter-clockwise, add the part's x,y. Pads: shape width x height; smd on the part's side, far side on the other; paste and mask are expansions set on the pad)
5-1437657-7 [mil] "CONN BARRIER STRIP 2CIRC .438"
  rect 150x150 hole 73: 1(438,0)
  round 150 hole 73: 2(0,0)
  silkscreen extent -260,-600 698,200
0603 [mm] "0603 from SM-752 data"
  rect 1x0.95 smd: 1(-0.8,0) 2(0.8,0)
  silkscreen extent -1.52,-0.69 1.52,0.69, body extent -0.87,-0.47 0.87,0.47, height 0.85
0805_HV [mil] "0805 with 30mil clearance between pads"
  rect 50x63 smd: 1(-40,0) 2(40,0)
  silkscreen extent -74,-40 74,40, body extent -43,-29 43,29, height 43
1206 [mm] "1206 from SM-752 data"
  rect 1.3x1.85 smd: 1(-1.45,0) 2(1.45,0)
  silkscreen extent -2.4,-1.21 2.4,1.21, body extent -1.7,-0.9 1.7,0.9, height 1.35
1210 [mm] "1210 from SM-752 data"
  rect 1.3x2.7 smd: 1(-1.45,0) 2(1.45,0)
  silkscreen extent -2.32,-1.57 2.32,1.57, body extent -1.7,-1.35 1.7,1.35, height 1.35
1210M [mm] "1210 from SM-752 data"
  rect 1.5x2.8 smd: 1(-1.55,0) 2(1.55,0)
  silkscreen extent -2.75,-1.85 2.75,1.85, body extent -1.7,-1.35 1.7,1.35, height 1.35
760390015 [mm]
  rect 1.27x0.66 smd: 1(0,0) 2(0,-2.54) 3(0,-5.08) 4(9.14,-5.08) 5(9.14,-2.54) 6(9.14,0)
  silkscreen extent -1,-6.35 10.2,2.1, body extent -1,-6.4 10.2,1.2, height 4.2
AssemblyNote [mil] "Assembly Note"
AssemblyNoteLabel [mil] "Assembly Note for PCB Labels"
CONN_61304021021 [mil]
  rect 60x60 hole 38: 1(952,50)
  round 60 hole 38: 2(952,-50) 3(852,50) 4(852,-50) 5(752,50) 6(752,-50) 7(652,50) 8(652,-50) 9(552,50) 10(552,-50) 11(452,50) 12(452,-50) 13(352,50) 14(352,-50) 15(252,50) 16(252,-50) 17(152,50) 18(152,-50) 19(52,50) 20(52,-50) 21(-48,50) 22(-48,-50) 23(-148,50) 24(-148,-50) 25(-248,50) 26(-248,-50) 27(-348,50) 28(-348,-50) 29(-448,50) 30(-448,-50) 31(-548,50) 32(-548,-50) 33(-648,50) 34(-648,-50) 35(-748,50) 36(-748,-50) 37(-848,50) 38(-848,-50) 39(-948,50) 40(-948,-50)
DBV0005A_N [mm] "SOT23, 5-Leads, Body 2.9x1.6mm, Pitch 0.95mm, Lead Span 2.8mm, IPC Medium Density"
  rect 1.1x0.65 smd: 1(-1.2,0.95) 2(-1.2,0) 3(-1.2,-0.95) 4(1.2,-0.95) 5(1.2,0.95)
  silkscreen extent -0.25,-1.55 0.25,1.55, body extent -1.42,-1.46 1.42,1.46, height 1.08
DGK8 [mil]
  rect 50x15 smd: 1(-78,40) 2(-78,14.4) 3(-78,-11.2) 4(-78,-36.8) 5(75.6,-36.8) 6(75.6,-11.2) 7(75.6,14.4) 8(75.6,40)
DW0016A_N [mm] "SOIC, 16-Leads, Body 10.3x7.5mm, Pitch 1.27mm, IPC Medium Density"
  oval 2.3x0.6 smd: 1(-4.55,4.445) 2(-4.55,3.175) 3(-4.55,1.905) 4(-4.55,0.635) 5(-4.55,-0.635) 6(-4.55,-1.905) 7(-4.55,-3.175) 8(-4.55,-4.445) 9(4.55,-4.445) 10(4.55,-3.175) 11(4.55,-1.905) 12(4.55,-0.635) 13(4.55,0.635) 14(4.55,1.905) 15(4.55,3.175) 16(4.55,4.445)
  silkscreen extent -4.67,-5.25 3,5.42, body extent -3.79,-5.25 3.8,5.25, height 2.64
FB0603 [mm]
  rect 0.95x1 smd: 1(-0.75,0) 2(0.75,0)
  silkscreen extent -0.8,-0.7 0.8,0.7
Fiducial10-20 [mm]
  round 1 smd paste+0 mask+0.5: 1(0,0)
  Top Layer keep-out circle w1.178: c0,0 r0.5
HDR100_1X2 [mil]
  rect 60x60 hole 38: 1(0,0)
  round 60 hole 38: 2(100,0)
  silkscreen extent -50,-50 150,50
Label_650x200 [mil] "Thermal Transfer Label"
  round 1 on Mech13: 0(0,0)
  silkscreen extent -325,-100 325,100, body extent -326,-101 326,101, height 1
LED0603AA [mil]
  rect 32x32 smd: 1(-32.48,0) 2(32.48,0)
  silkscreen extent -132,-25 11,25
MH3.2 [mil]
  round 20 / inner round 142 / far side round 20 hole 128 unplated mask+65: 1(0,0)
  silkscreen extent -120,-120 120,120
MSOP8(DGN) [mil]
  rect 50x15 smd: 1(-77,38) 2(-77,12.4) 3(-77,-13.2) 4(-77,-38.8) 5(76.6,-38.8) 6(76.6,-13.2) 7(76.6,12.4) 8(76.6,38)
  rect 60x75 smd: 9(0,-0.8)
  silkscreen extent -112,80 -87,105
powerDI123 [mm] "Diodes Inc recommended land pattern, document number DS30628 Rev. 6-2"
  rect 2.2x1.4 smd: 1(-1.275,0)
  rect 0.9x1.4 smd: 2(1.275,0)
  silkscreen extent -3.1,-1.09 1.76,1.09, body extent -2.37,-0.96 1.53,0.97, height 1
PWR4413D-R050F [mm] "PWR4413 Series Current Sense Resistors"
  round 2 hole 1.27: 1(0,0) 2(21.3,0)
  silkscreen extent -1.5,-2 22.75,2.03
R_TO-247 [mm]
  round 3 hole 1.8: 1(10.16,0) 2(0,0)
  silkscreen extent -2.76,-2.03 12.95,2.54
SM_RADIAL_5MM [mm] "Nichicon 5x5.8"
  rect 3x1.6 smd: 1(-2.2,0) 2(2.2,0)
  silkscreen extent -2.75,-2.75 2.75,2.75, body extent -2.75,-2.75 2.75,2.75, height 6.1
SO8 [mil]
  rect 80x26 smd: 1(-95,75) 2(-95,25) 3(-95,-25) 4(-95,-75) 5(94,-75) 6(94,-25) 7(94,25) 8(94,75)
  silkscreen extent -135,115 -95,155
SOD-123 [mm] "On Semi recommended land pattern"
  rect 0.915x1.22 smd: 1(-1.637,0) 2(1.637,0)
  silkscreen extent -2.74,-1.17 2.03,1.17, body extent -1.93,-0.9 1.93,0.9, height 1.35
SOT-323 [mm] "Zetex recommended land pattern.  March 2007"
  rect 0.8x0.6 smd: 1(-0.8,0.65) 2(-0.8,-0.65) 3(0.8,0)
  silkscreen extent -1.14,-1.22 1.09,1.49, body extent -1.13,-1.13 1.12,1.12, height 1.13
TI_Stacked_SolderMask_Small [mil]
  rect 0x0 smd paste-125 mask-125: 0(0,0)
  Top Layer region: 519 vertices and 0 holes, not listed, extent -418.39,-77.79 -237.37,98.14
  Top Layer region: 537 vertices and 1 holes, not listed, extent -104.32,-10.18 14.18,47.26
  Top Layer region: 271 vertices and 0 holes, not listed, extent 124.68,-98.14 197.38,-39.98
  Top Layer region: 193 vertices and 1 holes, not listed, extent 3.27,-98.14 65.79,-39.98
  Top Layer region: 243 vertices and 0 holes, not listed, extent -158.85,-98.14 -100.69,-39.98
  Top Layer region: 249 vertices and 0 holes, not listed, extent 255.54,-98.14 313.7,-39.98
  Top Layer region: -145.76,62.52 -145.04,62.52 -145.04,60.34 -144.31,60.34 -144.31,58.16 -143.58,58.16 -143.58,55.98 -142.86,55.98 -142.86,53.8 -142.13,53.8 -142.13,51.62 -141.4,51.62 -141.4,50.89 -142.13,50.89 -142.13,50.16 -143.58,50.16 -143.58,51.62 -144.31,51.62 -144.31,52.34 -145.04,52.34 -145.04,53.07 -145.76,53.07 -145.76,53.8 -147.22,53.8 -147.22,54.53 -147.94,54.53 -147.94,55.25 -150.13,55.25 -150.13,55.98 -153.03,55.98 -153.03,56.71 -168.3,56.71 -168.3,55.98 -169.03,55.98 -169.03,54.53 -169.75,54.53 -169.75,-2.91 -169.03,-2.91 -169.03,-5.09 -168.3,-5.09 -168.3,-5.82 -167.57,-5.82 -167.57,-6.54 -166.85,-6.54 -166.85,-7.27 -165.39,-7.27 -165.39,-8 -163.94,-8 -163.94,-10.18 -188.66,-10.18 -188.66,-8 -187.2,-8 -187.2,-7.27 -185.75,-7.27 -185.75,-6.54 -185.02,-6.54 -185.02,-5.82 -184.29,-5.82 -184.29,-5.09 -183.57,-5.09 -183.57,-2.18 -182.84,-2.18 -182.84,53.8 -183.57,53.8 -183.57,55.98 -185.02,55.98 -185.02,56.71 -199.56,56.71 -199.56,55.98 -202.47,55.98 -202.47,55.25 -204.65,55.25 -204.65,54.53 -205.38,54.53 -205.38,53.8 -206.83,53.8 -206.83,53.07 -207.56,53.07 -207.56,52.34 -208.29,52.34 -208.29,51.62 -209.01,51.62 -209.01,50.89 -209.74,50.89 -209.74,50.16 -210.47,50.16 -210.47,50.89 -211.19,50.89 -211.19,53.07 -210.47,53.07 -210.47,54.53 -209.74,54.53 -209.74,56.71 -209.01,56.71 -209.01,58.89 -208.29,58.89 -208.29,61.07 -207.56,61.07 -207.56,63.25 -206.83,63.25 -206.83,64.7 -145.76,64.7
  Top Layer region: 246.82,-41.44 247.54,-41.44 247.54,-42.89 248.27,-42.89 248.27,-45.07 249,-45.07 249,-47.26 249.72,-47.26 249.72,-48.71 250.45,-48.71 250.45,-50.89 251.18,-50.89 251.18,-53.07 250.45,-53.07 250.45,-53.8 249.72,-53.8 249.72,-53.07 249,-53.07 249,-52.34 248.27,-52.34 248.27,-51.62 246.82,-51.62 246.82,-50.89 246.09,-50.89 246.09,-50.16 245.36,-50.16 245.36,-49.44 244.64,-49.44 244.64,-48.71 243.18,-48.71 243.18,-47.98 241,-47.98 241,-47.26 238.09,-47.26 238.09,-46.53 222.83,-46.53 222.83,-47.26 220.64,-47.26 220.64,-48.71 219.92,-48.71 219.92,-63.98 237.37,-63.98 237.37,-63.25 239.55,-63.25 239.55,-62.52 240.27,-62.52 240.27,-61.8 241,-61.8 241,-60.34 241.73,-60.34 241.73,-58.89 243.91,-58.89 243.91,-74.88 241.73,-74.88 241.73,-73.43 241,-73.43 241,-71.97 240.27,-71.97 240.27,-71.25 238.09,-71.25 238.09,-70.52 219.92,-70.52 219.92,-88.69 220.64,-88.69 220.64,-90.15 241.73,-90.15 241.73,-89.42 244.64,-89.42 244.64,-88.69 246.09,-88.69 246.09,-87.97 247.54,-87.97 247.54,-87.24 248.27,-87.24 248.27,-86.51 249,-86.51 249,-85.79 249.72,-85.79 249.72,-85.06 250.45,-85.06 250.45,-84.33 251.18,-84.33 251.18,-83.61 251.91,-83.61 251.91,-82.88 253.36,-82.88 253.36,-83.61 254.09,-83.61 254.09,-85.06 253.36,-85.06 253.36,-86.51 252.63,-86.51 252.63,-88.69 251.91,-88.69 251.91,-90.15 251.18,-90.15 251.18,-92.33 250.45,-92.33 250.45,-93.78 249.72,-93.78 249.72,-95.96 249,-95.96 249,-97.42 201.74,-97.42 201.74,-95.24 203.2,-95.24 203.2,-94.51 204.65,-94.51 204.65,-93.78 206.1,-93.78 206.1,-93.06 206.83,-93.06 206.83,-90.88 207.56,-90.88 207.56,-45.8 206.83,-45.8 206.83,-44.35 206.1,-44.35 206.1,-43.62 205.38,-43.62 205.38,-42.89 203.92,-42.89 203.92,-42.17 201.74,-42.17 201.74,-39.98 246.82,-39.98
  Top Layer region: -110.14,45.8 -109.41,45.8 -109.41,44.35 -108.69,44.35 -108.69,42.17 -107.96,42.17 -107.96,39.98 -107.23,39.98 -107.23,37.8 -106.51,37.8 -106.51,36.35 -105.78,36.35 -105.78,33.44 -107.96,33.44 -107.96,34.17 -108.69,34.17 -108.69,34.9 -109.41,34.9 -109.41,35.62 -110.14,35.62 -110.14,36.35 -110.87,36.35 -110.87,37.08 -111.59,37.08 -111.59,37.8 -113.05,37.8 -113.05,38.53 -114.5,38.53 -114.5,39.26 -116.68,39.26 -116.68,39.98 -135.59,39.98 -135.59,39.26 -136.31,39.26 -136.31,38.53 -137.04,38.53 -137.04,23.26 -118.14,23.26 -118.14,23.99 -116.68,23.99 -116.68,24.72 -115.96,24.72 -115.96,26.17 -115.23,26.17 -115.23,27.63 -113.05,27.63 -113.05,11.63 -115.23,11.63 -115.23,13.81 -115.96,13.81 -115.96,14.54 -116.68,14.54 -116.68,15.27 -117.41,15.27 -117.41,15.99 -119.59,15.99 -119.59,16.72 -137.04,16.72 -137.04,-1.45 -136.31,-1.45 -136.31,-2.91 -134.13,-2.91 -134.13,-3.63 -118.86,-3.63 -118.86,-2.91 -113.78,-2.91 -113.78,-2.18 -111.59,-2.18 -111.59,-1.45 -110.14,-1.45 -110.14,-0.73 -109.41,-0.73 -109.41,0 -107.96,0 -107.96,0.73 -107.23,0.73 -107.23,1.45 -106.51,1.45 -106.51,2.18 -105.78,2.18 -105.78,2.91 -105.05,2.91 -105.05,3.63 -104.32,3.63 -104.32,4.36 -103.6,4.36 -103.6,3.63 -102.87,3.63 -102.87,2.18 -103.6,2.18 -103.6,0 -104.32,0 -104.32,-1.45 -105.05,-1.45 -105.05,-3.63 -105.78,-3.63 -105.78,-5.09 -106.51,-5.09 -106.51,-7.27 -107.23,-7.27 -107.23,-8.72 -107.96,-8.72 -107.96,-10.18 -155.21,-10.18 -155.21,-8 -153.03,-8 -153.03,-7.27 -151.58,-7.27 -151.58,-6.54 -150.85,-6.54 -150.85,-5.82 -150.13,-5.82 -150.13,-4.36 -149.4,-4.36 -149.4,41.44 -150.13,41.44 -150.13,42.89 -150.85,42.89 -150.85,43.62 -151.58,43.62 -151.58,44.35 -153.76,44.35 -153.76,45.07 -155.21,45.07 -155.21,47.26 -110.14,47.26
  Top Layer region: 293 vertices and 0 holes, not listed, extent 12,-10.9 59.25,47.98
  Top Layer region: 295 vertices and 0 holes, not listed, extent -98.51,-98.14 -51.25,-39.26
  Top Layer region: 283 vertices and 0 holes, not listed, extent 371.13,-98.14 418.39,-39.26
  Top Layer region: 121.05,-42.17 118.86,-42.17 118.86,-42.89 118.14,-42.89 118.14,-43.62 117.41,-43.62 117.41,-44.35 116.68,-44.35 116.68,-45.8 115.96,-45.8 115.96,-82.15 115.23,-82.15 115.23,-85.79 114.5,-85.79 114.5,-87.24 113.78,-87.24 113.78,-88.69 113.05,-88.69 113.05,-90.15 112.32,-90.15 112.32,-90.88 111.59,-90.88 111.59,-92.33 110.87,-92.33 110.87,-93.06 110.14,-93.06 110.14,-93.78 108.69,-93.78 108.69,-94.51 107.96,-94.51 107.96,-95.24 106.51,-95.24 106.51,-95.96 104.32,-95.96 104.32,-96.69 102.14,-96.69 102.14,-97.42 97.78,-97.42 97.78,-98.14 86.15,-98.14 86.15,-97.42 81.79,-97.42 81.79,-96.69 79.61,-96.69 79.61,-95.96 77.43,-95.96 77.43,-95.24 75.97,-95.24 75.97,-94.51 74.52,-94.51 74.52,-93.78 73.79,-93.78 73.79,-93.06 72.34,-93.06 72.34,-92.33 71.61,-92.33 71.61,-91.6 70.88,-91.6 70.88,-90.88 70.16,-90.88 70.16,-90.15 69.43,-90.15 69.43,-88.69 68.7,-88.69 68.7,-87.97 67.97,-87.97 67.97,-86.51 67.25,-86.51 67.25,-84.33 66.52,-84.33 66.52,-47.26 65.79,-47.26 65.79,-45.07 65.07,-45.07 65.07,-43.62 64.34,-43.62 64.34,-42.89 62.89,-42.89 62.89,-42.17 60.7,-42.17 60.7,-39.98 83.97,-39.98 83.97,-42.17 81.79,-42.17 81.79,-42.89 80.33,-42.89 80.33,-43.62 79.61,-43.62 79.61,-45.07 78.88,-45.07 78.88,-47.98 78.15,-47.98 78.15,-79.24 78.88,-79.24 78.88,-82.88 79.61,-82.88 79.61,-85.06 80.33,-85.06 80.33,-86.51 81.06,-86.51 81.06,-87.24 81.79,-87.24 81.79,-87.97 82.51,-87.97 82.51,-88.69 83.97,-88.69 83.97,-89.42 85.42,-89.42 85.42,-90.15 88.33,-90.15 88.33,-90.88 98.51,-90.88 98.51,-90.15 101.42,-90.15 101.42,-89.42 102.87,-89.42 102.87,-88.69 103.6,-88.69 103.6,-87.97 104.32,-87.97 104.32,-87.24 105.05,-87.24 105.05,-86.51 105.78,-86.51 105.78,-85.79 106.51,-85.79 106.51,-83.61 107.23,-83.61 107.23,-80.7 107.96,-80.7 107.96,-47.26 107.23,-47.26 107.23,-45.07 106.51,-45.07 106.51,-43.62 105.78,-43.62 105.78,-42.89 104.32,-42.89 104.32,-42.17 102.14,-42.17 102.14,-39.98 121.05,-39.98
  Top Layer region: -289.71,63.25 -290.44,63.25 -290.44,59.61 -291.16,59.61 -291.16,55.98 -291.89,55.98 -291.89,52.34 -292.62,52.34 -292.62,48.71 -293.34,48.71 -293.34,45.07 -294.07,45.07 -294.07,41.44 -294.8,41.44 -294.8,37.8 -295.53,37.8 -295.53,34.17 -296.25,34.17 -296.25,30.53 -296.98,30.53 -296.98,26.9 -297.71,26.9 -297.71,23.26 -298.43,23.26 -298.43,19.63 -299.16,19.63 -299.16,15.99 -299.89,15.99 -299.89,12.36 -300.61,12.36 -300.61,8.72 -301.34,8.72 -301.34,5.09 -302.07,5.09 -302.07,1.45 -302.8,1.45 -302.8,-2.18 -303.52,-2.18 -303.52,-5.82 -304.25,-5.82 -304.25,-9.45 -321.7,-9.45 -321.7,-7.27 -320.97,-7.27 -320.97,-3.63 -320.24,-3.63 -320.24,0 -319.52,0 -319.52,3.63 -318.79,3.63 -318.79,7.27 -318.06,7.27 -318.06,10.9 -317.34,10.9 -317.34,14.54 -316.61,14.54 -316.61,18.17 -315.88,18.17 -315.88,21.81 -315.15,21.81 -315.15,25.44 -314.43,25.44 -314.43,29.08 -313.7,29.08 -313.7,32.71 -312.97,32.71 -312.97,36.35 -312.25,36.35 -312.25,39.98 -311.52,39.98 -311.52,43.62 -310.79,43.62 -310.79,47.26 -310.07,47.26 -310.07,50.89 -309.34,50.89 -309.34,54.53 -308.61,54.53 -308.61,58.16 -307.88,58.16 -307.88,61.8 -307.16,61.8 -307.16,64.7 -289.71,64.7
  Top Layer region: -1.82,-42.17 -1.09,-42.17 -1.09,-45.07 -0.36,-45.07 -0.36,-47.26 0.36,-47.26 0.36,-49.44 1.09,-49.44 1.09,-51.62 1.82,-51.62 1.82,-55.25 0.36,-55.25 0.36,-54.53 -0.36,-54.53 -0.36,-53.8 -1.09,-53.8 -1.09,-53.07 -1.82,-53.07 -1.82,-52.34 -2.54,-52.34 -2.54,-51.62 -3.27,-51.62 -3.27,-50.89 -4,-50.89 -4,-50.16 -4.73,-50.16 -4.73,-49.44 -5.45,-49.44 -5.45,-48.71 -6.18,-48.71 -6.18,-47.98 -8.36,-47.98 -8.36,-47.26 -11.27,-47.26 -11.27,-46.53 -17.81,-46.53 -17.81,-47.26 -18.54,-47.26 -18.54,-47.98 -19.27,-47.98 -19.27,-90.88 -18.54,-90.88 -18.54,-93.06 -17.81,-93.06 -17.81,-93.78 -16.36,-93.78 -16.36,-94.51 -14.18,-94.51 -14.18,-95.24 -12.72,-95.24 -12.72,-97.42 -37.44,-97.42 -37.44,-95.24 -36.71,-95.24 -36.71,-94.51 -34.53,-94.51 -34.53,-93.78 -33.08,-93.78 -33.08,-93.06 -32.35,-93.06 -32.35,-91.6 -31.62,-91.6 -31.62,-47.26 -33.08,-47.26 -33.08,-46.53 -39.62,-46.53 -39.62,-47.26 -42.53,-47.26 -42.53,-47.98 -43.98,-47.98 -43.98,-48.71 -44.71,-48.71 -44.71,-49.44 -46.16,-49.44 -46.16,-50.16 -46.89,-50.16 -46.89,-50.89 -47.62,-50.89 -47.62,-52.34 -48.35,-52.34 -48.35,-53.07 -49.07,-53.07 -49.07,-53.8 -49.8,-53.8 -49.8,-54.53 -50.53,-54.53 -50.53,-55.25 -51.98,-55.25 -51.98,-54.53 -52.71,-54.53 -52.71,-53.8 -51.98,-53.8 -51.98,-51.62 -51.25,-51.62 -51.25,-49.44 -50.53,-49.44 -50.53,-47.26 -49.8,-47.26 -49.8,-44.35 -49.07,-44.35 -49.07,-42.17 -48.35,-42.17 -48.35,-39.98 -1.82,-39.98
  Top Layer region: -163.21,-23.99 -163.94,-23.99 -163.94,-24.72 -166.12,-24.72 -166.12,-25.44 -167.57,-25.44 -167.57,-26.17 -168.3,-26.17 -168.3,-26.9 -169.03,-26.9 -169.03,-29.08 -169.75,-29.08 -169.75,-90.15 -169.03,-90.15 -169.03,-92.33 -168.3,-92.33 -168.3,-93.06 -167.57,-93.06 -167.57,-93.78 -166.12,-93.78 -166.12,-94.51 -163.94,-94.51 -163.94,-95.24 -163.21,-95.24 -163.21,-97.42 -189.38,-97.42 -189.38,-95.24 -188.66,-95.24 -188.66,-94.51 -186.48,-94.51 -186.48,-93.78 -185.02,-93.78 -185.02,-93.06 -184.29,-93.06 -184.29,-91.6 -183.57,-91.6 -183.57,-89.42 -182.84,-89.42 -182.84,-29.81 -183.57,-29.81 -183.57,-27.63 -184.29,-27.63 -184.29,-26.17 -185.75,-26.17 -185.75,-25.44 -186.48,-25.44 -186.48,-24.72 -188.66,-24.72 -188.66,-23.99 -189.38,-23.99 -189.38,-22.54 -163.21,-22.54
  Top Layer region: 364.59,-40.71 365.32,-40.71 365.32,-42.89 366.04,-42.89 366.04,-45.07 366.77,-45.07 366.77,-47.26 367.5,-47.26 367.5,-50.16 368.23,-50.16 368.23,-52.34 368.95,-52.34 368.95,-55.25 366.77,-55.25 366.77,-53.8 366.04,-53.8 366.04,-53.07 365.32,-53.07 365.32,-52.34 364.59,-52.34 364.59,-51.62 363.86,-51.62 363.86,-50.89 363.14,-50.89 363.14,-50.16 362.41,-50.16 362.41,-49.44 361.68,-49.44 361.68,-48.71 360.96,-48.71 360.96,-47.98 358.77,-47.98 358.77,-47.26 355.87,-47.26 355.87,-46.53 349.32,-46.53 349.32,-47.26 348.6,-47.26 348.6,-47.98 347.87,-47.98 347.87,-91.6 348.6,-91.6 348.6,-93.06 349.32,-93.06 349.32,-93.78 350.78,-93.78 350.78,-94.51 352.96,-94.51 352.96,-95.24 353.69,-95.24 353.69,-97.42 329.69,-97.42 329.69,-95.24 330.42,-95.24 330.42,-94.51 332.6,-94.51 332.6,-93.78 334.06,-93.78 334.06,-93.06 334.78,-93.06 334.78,-91.6 335.51,-91.6 335.51,-47.98 334.78,-47.98 334.78,-47.26 334.06,-47.26 334.06,-46.53 327.51,-46.53 327.51,-47.26 324.61,-47.26 324.61,-47.98 323.15,-47.98 323.15,-48.71 321.7,-48.71 321.7,-49.44 320.97,-49.44 320.97,-50.16 320.24,-50.16 320.24,-50.89 319.52,-50.89 319.52,-51.62 318.79,-51.62 318.79,-53.07 318.06,-53.07 318.06,-53.8 317.34,-53.8 317.34,-54.53 316.61,-54.53 316.61,-55.25 315.15,-55.25 315.15,-54.53 314.43,-54.53 314.43,-53.8 315.15,-53.8 315.15,-51.62 315.88,-51.62 315.88,-48.71 316.61,-48.71 316.61,-46.53 317.34,-46.53 317.34,-44.35 318.06,-44.35 318.06,-42.17 318.79,-42.17 318.79,-39.98 364.59,-39.98
  Top Layer region: -285.35,85.79 -286.07,85.79 -286.07,82.15 -286.8,82.15 -286.8,78.52 -287.53,78.52 -287.53,74.88 -288.26,74.88 -288.26,71.97 -305.7,71.97 -305.7,73.43 -304.98,73.43 -304.98,77.06 -304.25,77.06 -304.25,80.7 -303.52,80.7 -303.52,84.33 -302.8,84.33 -302.8,87.97 -302.07,87.97 -302.07,88.69 -285.35,88.69
TP-040_RND [mil]
  round 70 / inner round 62 / far side round 62 hole 40: 1(0,0)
